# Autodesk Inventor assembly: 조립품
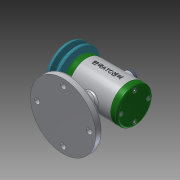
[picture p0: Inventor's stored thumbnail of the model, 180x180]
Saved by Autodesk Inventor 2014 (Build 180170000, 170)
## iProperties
Created: 2018-12
Part Number: 조립품
Document SubType Name: Assembly
Designer: 601-22
Author: 601-22
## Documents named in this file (15)
- C:\Users\601-22\Desktop\481208V1005\조립품.iam
- C:\Users\601-22\Desktop\481208V1005\본체.ipt
- C:\Users\601-22\Desktop\481208V1005\축.ipt
- C:\Users\601-22\Desktop\481208V1005\키 3 x 3 x 12.ipt
- C:\Users\601-22\Desktop\481208V1005\베어링 15 x 32 x 9.ipt
- C:\Users\601-22\Desktop\481208V1005\오일 실 15 25 7.ipt
- C:\Users\601-22\Desktop\481208V1005\앞커버.ipt
- C:\Users\601-22\Desktop\481208V1005\뒤커버.ipt
- C:\Users\601-22\Desktop\481208V1005\V벨트풀리.ipt
- C:\Users\601-22\Desktop\481208V1005\너트 M8.ipt
- 너트 M8.ipt
- C:\Users\601-22\Desktop\481208V1005\스프링와셔 8.ipt
- C:\Users\601-22\Desktop\481208V1005\와셔 8x17.ipt
- C:\Users\601-22\Desktop\481208V1005\볼트 M4 x 12.ipt
- C:\Users\601-22\Desktop\481208V1005\고무캡.ipt
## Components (2 placed, 2 different names)
1. V벨트풀리:1
2. 고무캡:1
